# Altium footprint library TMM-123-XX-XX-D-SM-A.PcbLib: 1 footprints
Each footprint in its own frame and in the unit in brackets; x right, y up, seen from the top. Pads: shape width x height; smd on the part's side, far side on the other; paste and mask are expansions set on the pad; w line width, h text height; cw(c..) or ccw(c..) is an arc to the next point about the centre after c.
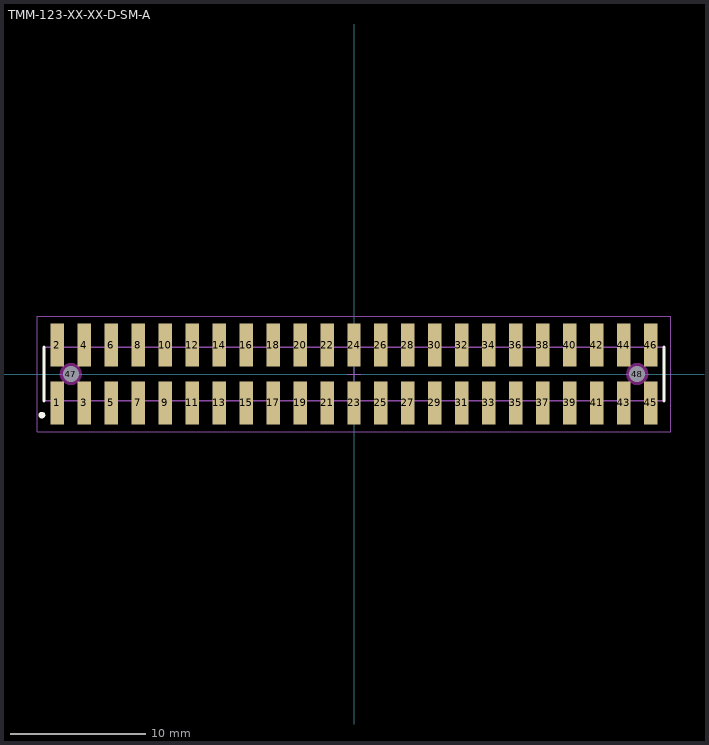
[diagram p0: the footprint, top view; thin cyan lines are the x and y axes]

## TMM-123-XX-XX-D-SM-A [mm] "2.00mm pitch, 46 pin, terminal strip; double row, w/alignment pins, SMT"
height 2.77
pads (48):
  rect 1x3.2 smd mask+0: 1(-22,-2.15) 2(-22,2.15) 3(-20,-2.15) 4(-20,2.15) 5(-18,-2.15) 6(-18,2.15) 7(-16,-2.15) 8(-16,2.15) 9(-14,-2.15) 10(-14,2.15) 11(-12,-2.15) 12(-12,2.15) 13(-10,-2.15) 14(-10,2.15) 15(-8,-2.15) 16(-8,2.15) 17(-6,-2.15) 18(-6,2.15) 19(-4,-2.15) 20(-4,2.15) 21(-2,-2.15) 22(-2,2.15) 23(0,-2.15) 24(0,2.15) 25(2,-2.15) 26(2,2.15) 27(4,-2.15) 28(4,2.15) 29(6,-2.15) 30(6,2.15) 31(8,-2.15) 32(8,2.15) 33(10,-2.15) 34(10,2.15) 35(12,-2.15) 36(12,2.15) 37(14,-2.15) 38(14,2.15) 39(16,-2.15) 40(16,2.15) 41(18,-2.15) 42(18,2.15) 43(20,-2.15) 44(20,2.15) 45(22,-2.15) 46(22,2.15)
  round 1 hole 1.2 unplated mask+0: 47(-21,0) 48(21,0)
Top Overlay:
  circle w0.25: c-23.15,-3.05 r0.125
  lines w0.2: -23,-2 -23,2 ; 23,-2 23,2
Keep-Out Layer:
  pour cut-out: 21.807,0 21.779,0.209 21.699,0.403 21.571,0.571 21.403,0.699 21.209,0.779 21,0.807 20.791,0.779 20.597,0.699 20.429,0.571 20.301,0.403 20.221,0.209 20.193,0 20.221,-0.209 20.301,-0.403 20.429,-0.571 20.597,-0.699 20.791,-0.779 21,-0.807 21.209,-0.779 21.403,-0.699 21.571,-0.571 21.699,-0.403 21.779,-0.209
  pour cut-out: -20.193,0 -20.221,0.209 -20.301,0.403 -20.429,0.571 -20.597,0.699 -20.791,0.779 -21,0.807 -21.209,0.779 -21.403,0.699 -21.571,0.571 -21.699,0.403 -21.779,0.209 -21.807,0 -21.779,-0.209 -21.699,-0.403 -21.571,-0.571 -21.403,-0.699 -21.209,-0.779 -21,-0.807 -20.791,-0.779 -20.597,-0.699 -20.429,-0.571 -20.301,-0.403 -20.221,-0.209
Mechanical 12:
  lines w0.001: -23,-2 -23,2 23,2 23,-2 -23,-2
Mechanical 13:
  lines w0.1: -23,-2 -23,2 23,2 23,-2 -23,-2
  text ".Designator" at 0,-0.127 h1.52
Mechanical 15:
  lines w0.05: -0.5,0 0.5,0 ; 0,-0.5 0,0.5 ; -23.5,-4.3 -23.5,4.3 23.5,4.3 23.5,-4.3 -23.5,-4.3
